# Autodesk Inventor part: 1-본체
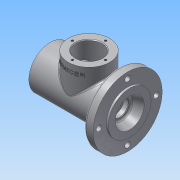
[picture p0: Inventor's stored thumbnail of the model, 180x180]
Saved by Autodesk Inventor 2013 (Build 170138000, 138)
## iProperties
Created: 2016-08
Part Number: 1-본체
Material: 알루미늄 6061
Document SubType Name: Modeling
Designer: Administrator
Density: 2.71 g/cm^3
Mass: 766.33 g
Surface Area: 624.874 cm^2
Volume: 282.779 cm^3
Author: Administrator
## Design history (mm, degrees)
sketch "스케치1"
  geometry: L1 (-57.5, 0)-(57.5, 0); L2 (-57.5, 31)-(41.5, 31); L3 (41.5, 31)-(41.5, 50); L4 (41.5, 50)-(54.5, 50); L5 (54.5, 50)-(54.5, 31); L6 (54.5, 31)-(57.5, 31); L7 (57.5, 21)-(57.5, 31); L8 (-57.5, 31)-(-57.5, 21); L9 (-57.5, 21)-(-48.5, 21); L10 (-48.5, 21)-(-48.5, 24); L11 (-48.5, 24)-(-45.5, 24); L12 (-45.5, 24)-(-45.5, 20); L13 (-45.5, 20)-(-36.5, 20); L14 (-36.5, 20)-(-36.5, 17.5); L15 (-36.5, 17.5)-(-33.25, 17.5); L16 (-33.25, 17.5)-(-33.25, 18.5); L17 (-31.5, 18.5)-(-31.5, 17.5); L18 (-31.5, 17.5)-(-21.5, 17.5); L19 (-20.5, 18.5)-(-20.5, 23); L20 (-17.5, 26)-(14.5, 26); L21 (17.5, 23)-(17.5, 18.5); L22 (18.5, 17.5)-(28.2, 17.5); L23 (28.5, 17.2)-(28.5, 16.5); L24 (28.5, 16.5)-(30.5, 16.5); L25 (33.5, 13.5)-(33.5, 10); L26 (33.5, 10)-(36.2, 10); L27 (36.2, 10)-(36.2, 12.2); L28 (36.5, 12.5)-(42.8, 12.5); L29 (43.5, 12.904)-(43.5, 13.886); L30 (45.491, 16.711)-(57.5, 21); L31 (-33.25, 18.5)-(-31.5, 18.5); L32 (-20.5, 18.5)-(-21.5, 17.5); L33 (17.5, 18.5)-(18.5, 17.5); L34 (42.8, 12.5)-(43.5, 12.904); A1 r 3 centre (-17.5, 23) between (-17.5, 26) and (-20.5, 23); A2 r 3 centre (14.5, 23) between (17.5, 23) and (14.5, 26); A3 r 3 centre (30.5, 13.5) between (33.5, 13.5) and (30.5, 16.5); A4 r 0.3 centre (28.2, 17.2) between (28.5, 17.2) and (28.2, 17.5); A5 r 0.3 centre (36.5, 12.2) between (36.5, 12.5) and (36.2, 12.2); A6 r 3 centre (46.5, 13.886) between (45.491, 16.711) and (43.5, 13.886); 11 further points
  constraints: 68 end point, 22 parallel, 18 point on line, 12 point on circle, 12 tangent, 6 centre point, 6 perpendicular, 2 horizontal, 2 vertical alignment, 1 coincident, 1 equal radius, 1 midpoint
  dimensions: "d0" = 115 distance of L1.start L1.end; "d2" = 62 diameter of L2 L1; "d3" = 100 diameter of L4 L1; "d4" = 13 distance of L3.end L4.end; "d5" = 3 distance between parallel lines of L5 L7; "d6" = 62 diameter of L6 L1; "d7" = 52 diameter of L20 L1; "d8" = 42 diameter of L9 L1; "d9" = 48 diameter of L11 L1; "d12" = 40 diameter of L13 L1; "d13" = 35 diameter of L15 L1; "d15" = 35 diameter of L18 L1; "d19" = 42 diameter of L7.start L1; "d20" = 14 horizontal distance of point (43.5, 16) L7.start; "d21" = 32 diameter of point (43.5, 16) L1; "d22" = 7.3 distance of point (36.2, 12.5) point (43.5, 12.5); "d23" = 25 diameter of L28 L1; "d24" = 2.7 distance of L25.end L26.end; "d25" = 20 diameter of L26 L1; "d26" = 5 distance of L23.end point (33.5, 16.5); "d27" = 33 diameter of L24 L1; "d28" = 35 diameter of L22 L1; "d29" = 60 distance of point (28.5, 17.5) L17.end; "d30" = 38 distance of point (-20.5, 26) point (17.5, 26); "d31" = 3.25 distance of L14.end L15.end; "d32" = 1.75 distance of L16.end L17.start; "d33" = 12 distance between parallel lines of L8 L12; "d34" = 3 distance of L10.end L11.end; "d35" = 37 diameter of L31 L1; "d36" = 11 distance of L17.end point (-20.5, 17.5); "d37" = 3 radius of A1; "d38" = 1 distance of L19.start point (-20.5, 17.5); "d39" = 1 distance of L18.end point (-20.5, 17.5) (= d38); "d40" = 1 distance of L21.end point (17.5, 17.5); "d41" = 1 distance of L22.start point (17.5, 17.5) (= d40); "d42" = 3 radius of A3; "d43" = 0.3 radius of A4; "d44" = 0.3 radius of A5; "d45" = 0.7 distance of L28.end point (43.5, 12.5); "d46" = 30 deg angle of L28 L34; "d47" = 3 radius of A6
revolve "회전1" sketch "스케치1" stored, may be unused: angle "d48" = 90 deg
feature "스레드1" dims "d49" = 10, "d50" = 0
node "작업 평면1"
sketch "스케치2"
  geometry: L1 (-57.5, -31)-(-57.5, 31) reference; C1 r 30 at (-1.5, 0); 2 further points
  constraints: 1 centre point, 1 horizontal alignment, 1 midpoint
  dimensions: "d52" = 60 diameter of C1; "d54" = 56 distance from line of C1.centre L1
extrude "돌출1" join sketch "스케치2" stored distance "d55" = 10; taper "d56" = 0 deg
sketch "스케치3"
  geometry: C1 r 30 at (0, 0) reference; C2 r 19 at (0, 0); 1 further point
  constraints: 1 centre point, 1 coincident
  dimensions: "d57" = 38 diameter of C2
extrude "돌출2" cut sketch "스케치3" distance "d59" = 50; taper "d60" = 0 deg
sketch "스케치4"
  geometry: C1 r 50 at (0, 0) reference; C2 r 31 at (0, 0) reference; C3 r 4 at (0, 41.5); C4 r 4 at (-41.5, 0); C5 r 4 at (0, -41.5); C6 r 4 at (41.5, 0); A1 r 41.5 centre (0, 0) between (0, 41.5) and (-41.5, 0)
  constraints: 5 centre point, 4 point on circle, 3 equal radius, 2 horizontal alignment, 2 vertical alignment, 1 coincident
  dimensions: "d61" = 83 diameter of A1; "d63" = 8 diameter of C3
extrude "돌출3" cut sketch "스케치4" stored distance "d64" = 10; taper "d65" = 0 deg
sketch "스케치5"
  geometry: C1 r 19 at (0, 0) reference; C2 r 30 at (0, 0) reference; A1 r 24 centre (0, 0) between (0, 24) and (-24, 0); 3 further points
  constraints: 4 point on circle, 2 horizontal alignment, 2 vertical alignment, 1 centre point, 1 coincident
  dimensions: "d66" = 48 diameter of A1
hole "구멍1" sketch "스케치5" at (0, 24), (-24, 0), (0, -24), (24, 0) diameter "d68" = 3.242; stored, may be unused: countersink angle "d72" = 90 deg, drill point angle "d74" = 118 deg; dims "d69" = 8, "d70" = 4, "d71" = 2, "d73" = 10
fillet "모깎기1" dims "d75" = 3
chamfer "모따기1" distance "d76" = 1; stored, may be unused: second distance "d77" = 2, angle "d78" = 45 deg
fillet "모깎기2" dims "d79" = 3
node "작업 평면2"
sketch "스케치6"
  geometry: L1 (-31.5, 49)-(28.5, 49) reference; 3 further points
  constraints: 1 midpoint, 1 vertical alignment, 1 other
  dimensions: "d81" = 10 distance from line of point (-1.5, 39) L1
feature "엠보싱1" sketch "스케치6" dims "d82" = 0.5, "d83" = 0
fillet "모깎기3" dims "d84" = 3
node "솔리드1"
other parameters: "d51" = 49
